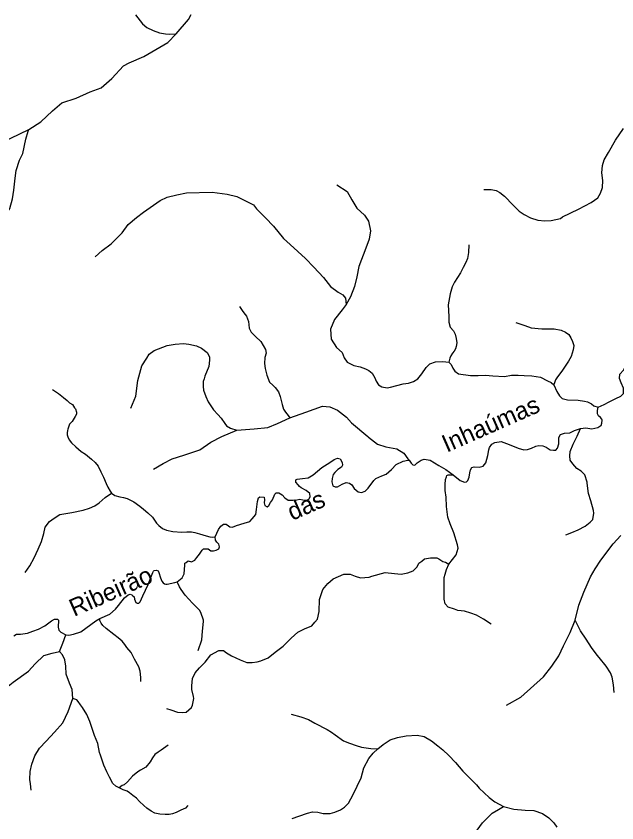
# Model space of a CAD drawing. Extents: x 436.3 to 500.4, y 8231 to 8286.4.
# Drawn here: x 465.31 to 472.13, y 8266.93 to 8276.08 of the extents above; entities that cross this region are included whole.
import ezdxf
from ezdxf.enums import TextEntityAlignment as Align

# ---------------------------------------------------------------- set-up
doc = ezdxf.new("R2010")
doc.units = 0
doc.header["$LTSCALE"] = 0.08
doc.linetypes.add('LONG_DASHED', pattern=[7.5, 6, -1.5])
doc.layers.add('61', color=7, linetype='Continuous')
doc.layers.add('9', color=7, linetype='LONG_DASHED', lineweight=25)

msp = doc.modelspace()

# ---------------------------------------------------------------- linework, layer by layer
at = {"layer": '9'}
for points in [[(466.6698, 8276.0975), (466.7493, 8275.9956), (466.7975, 8275.9512), (466.8677, 8275.918), (466.9416, 8275.8923), (467.0083, 8275.8813), (467.0526, 8275.8777), (467.1302, 8275.8815)], [(467.1302, 8275.8815), (467.2683, 8276.0433), (467.3012, 8276.101)], [(465.4558, 8274.796), (465.594, 8274.8835), (465.727, 8275.0083), (465.8334, 8275.0975), (465.993, 8275.151), (466.1526, 8275.2225), (466.2767, 8275.2671), (466.4009, 8275.3741), (466.5337, 8275.5167), (466.5958, 8275.5524), (466.7643, 8275.6238), (467.0342, 8275.7812), (467.1302, 8275.8815)], [(463.7903, 8273.8492), (463.8702, 8273.9116), (463.9855, 8273.9917), (464.1185, 8274.1253), (464.2072, 8274.1699), (464.3226, 8274.2323), (464.4823, 8274.3213), (464.6331, 8274.4104), (464.7356, 8274.4873), (464.9259, 8274.5708), (465.1211, 8274.6334), (465.2541, 8274.6958), (465.4558, 8274.796)], [(465.1525, 8273.7927), (465.2093, 8273.8456), (465.2399, 8273.8983), (465.2703, 8274.0082), (465.2877, 8274.1049), (465.3006, 8274.2411), (465.3136, 8274.3291), (465.3528, 8274.4478), (465.3877, 8274.5225), (465.4225, 8274.6851), (465.4486, 8274.7773), (465.4558, 8274.796)], [(470.6236, 8274.1144), (470.7041, 8274.1144), (470.7615, 8274.1029), (470.8038, 8274.0798), (470.8574, 8274.0374), (470.9531, 8273.9374), (471.0221, 8273.8682), (471.0796, 8273.8296), (471.1524, 8273.7912), (471.2329, 8273.7643), (471.3134, 8273.7567), (471.3862, 8273.7605), (471.4936, 8273.7837), (471.5165, 8273.803), (471.6968, 8273.8919), (471.8387, 8273.9652), (471.9154, 8274.0192), (471.9461, 8274.0731), (471.9691, 8274.1348), (471.973, 8274.2157), (471.9615, 8274.3042), (471.9703, 8274.3868), (471.9895, 8274.4522), (472.0356, 8274.5331), (472.1161, 8274.6757), (472.2082, 8274.8067)], [(468.9552, 8274.166), (469.072, 8274.0926), (469.1231, 8273.9972), (469.1815, 8273.9018), (469.2692, 8273.8211), (469.313, 8273.755), (469.3348, 8273.6449), (469.3203, 8273.5496), (469.2837, 8273.4468), (469.2035, 8273.2413), (469.1815, 8273.1238), (469.1523, 8273.0137), (469.1085, 8272.8963), (469.0574, 8272.8082)], [(466.2111, 8273.349), (466.2913, 8273.4225), (466.3934, 8273.496), (466.5175, 8273.6208), (466.583, 8273.7163), (466.6779, 8273.7972), (466.7582, 8273.856), (466.9479, 8273.9883), (467.0281, 8274.0251), (467.1375, 8274.0547), (467.247, 8274.0768), (467.539, 8274.0844), (467.707, 8274.0626), (467.8165, 8274.0334), (468.0063, 8273.9381), (468.0428, 8273.894), (468.145, 8273.7914), (468.2327, 8273.696), (468.3495, 8273.5566), (468.4225, 8273.4906), (468.5101, 8273.4098), (468.5977, 8273.3292), (468.6925, 8273.2338), (468.8021, 8273.1164), (468.8823, 8273.0137), (468.9698, 8272.9476), (469.0209, 8272.9183), (469.0501, 8272.8816), (469.0574, 8272.8082)], [(470.4501, 8273.4879), (470.4463, 8273.3997), (470.4348, 8273.3306), (470.4157, 8273.2846), (470.389, 8273.2272), (470.3568, 8273.1695), (470.2876, 8273.0616), (470.2608, 8273.0076), (470.2378, 8272.9305), (470.2185, 8272.8033), (470.226, 8272.6723), (470.226, 8272.6068), (470.2413, 8272.5528), (470.2758, 8272.5105), (470.295, 8272.4719), (470.3064, 8272.4218), (470.3141, 8272.3756), (470.3064, 8272.3332), (470.2986, 8272.3062), (470.2834, 8272.2792), (470.268, 8272.2561), (470.2488, 8272.2253), (470.2373, 8272.1983), (470.2248, 8272.1555)], [(467.8468, 8272.7854), (467.8875, 8272.7309), (467.9146, 8272.6946), (467.9281, 8272.6764), (467.9507, 8272.6174), (467.9597, 8272.5401), (467.9823, 8272.4946), (468.032, 8272.4447), (468.0908, 8272.3901), (468.1179, 8272.3448), (468.145, 8272.2993), (468.1495, 8272.2584), (468.1359, 8272.2084), (468.1314, 8272.1403), (468.1403, 8272.0811), (468.1585, 8272.0085), (468.1901, 8271.9267), (468.2262, 8271.895), (468.2533, 8271.8677), (468.2894, 8271.8177), (468.312, 8271.7632), (468.3345, 8271.6724), (468.3481, 8271.6224), (468.3707, 8271.5861), (468.4023, 8271.5497), (468.4217, 8271.5227)], [(469.0574, 8272.8082), (469.0139, 8272.7471), (468.9264, 8272.637), (468.883, 8272.5289), (468.8898, 8272.4169), (468.9481, 8272.3215), (469.0137, 8272.2628), (469.0356, 8272.2041), (469.0721, 8272.1529), (469.145, 8272.1161), (469.218, 8272.1015), (469.278, 8272.0784), (469.3163, 8272.0591), (469.3545, 8272.0283), (469.3852, 8271.9782), (469.4005, 8271.9398), (469.4273, 8271.8973), (469.4656, 8271.8743), (469.5231, 8271.8627), (469.5614, 8271.8705), (469.7071, 8271.909), (469.7684, 8271.9167), (469.8221, 8271.936), (469.872, 8271.9668), (469.918, 8272.0207), (469.9679, 8272.0939), (470.0101, 8272.1362), (470.0714, 8272.1594), (470.1557, 8272.1632), (470.2248, 8272.1555)], [(470.9866, 8272.6059), (471.0862, 8272.5712), (471.1591, 8272.5443), (471.2819, 8272.5328), (471.42, 8272.5329), (471.5006, 8272.5175), (471.5504, 8272.4944), (471.5849, 8272.4674), (471.6078, 8272.429), (471.627, 8272.3904), (471.6423, 8272.3441), (471.6346, 8272.2941), (471.6115, 8272.217), (471.5846, 8272.1669), (471.5077, 8272.0513), (471.4578, 8271.9896), (471.4347, 8271.955), (471.4155, 8271.8972)], [(466.6156, 8271.6332), (466.6704, 8271.7669), (466.6939, 8271.9475), (466.7408, 8272.1126), (466.7955, 8272.1991), (466.8238, 8272.2468), (466.8799, 8272.2879), (467.0278, 8272.3445), (467.1196, 8272.3599), (467.2115, 8272.3651), (467.2726, 8272.36), (467.3594, 8272.3396), (467.4154, 8272.314), (467.4817, 8272.2628), (467.5073, 8272.2167), (467.5073, 8272.1756), (467.5021, 8272.1038), (467.4562, 8271.9962), (467.446, 8271.9653), (467.4358, 8271.9346), (467.4358, 8271.8782), (467.4408, 8271.8372), (467.4662, 8271.7654), (467.4917, 8271.7039), (467.5529, 8271.6117), (467.6039, 8271.5605), (467.6395, 8271.5195), (467.6803, 8271.458), (467.7007, 8271.4324), (467.7466, 8271.4069), (467.8198, 8271.381)], [(471.9178, 8271.643), (471.9891, 8271.6733), (472.043, 8271.7029), (472.1216, 8271.7424), (472.1762, 8271.7697), (472.2056, 8271.7993), (472.2056, 8271.8583), (472.1812, 8271.9209), (472.1617, 8271.97), (472.1666, 8272.0193), (472.2059, 8272.0637), (472.2305, 8272.1081), (472.26, 8272.1573), (472.2747, 8272.1968), (472.2894, 8272.2264), (472.3238, 8272.2461), (472.3975, 8272.2462), (472.4465, 8272.2316), (472.5043, 8272.1873)], [(470.2248, 8272.1555), (470.2516, 8272.1286), (470.2707, 8272.0863), (470.2937, 8272.0515), (470.3359, 8272.0207), (470.4722, 8272.0043), (470.5566, 8272.0043), (470.6409, 8272.0082), (470.7253, 8272.0005), (470.8556, 8271.9928), (470.9362, 8272.0083), (471.0129, 8272.0083), (471.078, 8272.0044), (471.1663, 8272.0006), (471.266, 8271.9853), (471.3427, 8271.9429), (471.3849, 8271.9237), (471.4155, 8271.8972)], [(465.7249, 8271.8458), (465.7952, 8271.7971), (465.8492, 8271.7537), (465.8925, 8271.7211), (465.9194, 8271.694), (465.952, 8271.6723), (465.9743, 8271.6374), (465.9864, 8271.6237), (465.9985, 8271.5856), (465.9985, 8271.5626), (465.9818, 8271.5382), (465.9484, 8271.4817), (465.9193, 8271.4493), (465.9014, 8271.3959), (465.8971, 8271.3801), (465.8928, 8271.3531), (465.8928, 8271.3289), (465.8985, 8271.3089), (465.9141, 8271.2748), (465.9425, 8271.2391), (465.9907, 8271.1936), (466.0503, 8271.1423), (466.0999, 8271.1096), (466.168, 8271.0527), (466.2106, 8271.0156), (466.2431, 8270.973), (466.2747, 8270.9106), (466.3045, 8270.848), (466.3356, 8270.7769), (466.3554, 8270.737), (466.3809, 8270.6914), (466.3947, 8270.6664)], [(471.4155, 8271.8972), (471.45, 8271.8198), (471.4806, 8271.7736), (471.5112, 8271.7428), (471.5726, 8271.7275), (471.6915, 8271.7237), (471.7644, 8271.7122), (471.7989, 8271.7045), (471.8449, 8271.6815), (471.8718, 8271.6584), (471.9178, 8271.643)], [(468.4217, 8271.5227), (468.6015, 8271.5856), (468.7891, 8271.6564), (468.8751, 8271.6486), (468.961, 8271.6093), (469.0646, 8271.5303), (469.1193, 8271.4675), (469.3068, 8271.3104), (469.3146, 8271.3026), (469.4162, 8271.2241), (469.5099, 8271.1927), (469.635, 8271.1692), (469.7131, 8271.1221), (469.76, 8271.0593), (469.774, 8271.0423)], [(471.719, 8271.4025), (471.7778, 8271.4074), (471.8464, 8271.3977), (471.9152, 8271.4125), (471.9397, 8271.4273), (471.9544, 8271.4371), (471.9594, 8271.4618), (471.9643, 8271.4962), (471.9594, 8271.506), (471.9447, 8271.5256), (471.9251, 8271.5454), (471.9104, 8271.5699), (471.9105, 8271.6043), (471.9178, 8271.643)], [(467.8198, 8271.381), (468.0151, 8271.3969), (468.1715, 8271.4126), (468.2809, 8271.4598), (468.4217, 8271.5227)], [(466.8738, 8270.9408), (466.9832, 8271.0036), (467.0849, 8271.0587), (467.2177, 8271.098), (467.3976, 8271.1609), (467.5227, 8271.2473), (467.6478, 8271.3103), (467.8198, 8271.381)], [(470.2736, 8270.8743), (470.3518, 8270.8104), (470.4009, 8270.7908), (470.424, 8270.7972), (470.4406, 8270.8119), (470.4553, 8270.8489), (470.4647, 8270.8989), (470.4701, 8270.9338), (470.4843, 8270.9579), (470.5138, 8270.9678), (470.5696, 8270.9629), (470.6138, 8270.9729), (470.6433, 8271.0122), (470.6678, 8271.0958), (470.6777, 8271.1598), (470.6875, 8271.1843), (470.712, 8271.2236), (470.7464, 8271.2433), (470.82, 8271.2533), (470.9082, 8271.2188), (471.011, 8271.1795), (471.0748, 8271.1599), (471.1189, 8271.1649), (471.163, 8271.1796), (471.2121, 8271.1993), (471.2464, 8271.2091), (471.2906, 8271.2043), (471.3297, 8271.1895), (471.3738, 8271.1601), (471.413, 8271.1551), (471.4376, 8271.1551), (471.4572, 8271.1798), (471.472, 8271.2289), (471.4721, 8271.2978), (471.4933, 8271.3334), (471.5374, 8271.3483), (471.5963, 8271.3532), (471.6503, 8271.3778), (471.719, 8271.4025)], [(471.5523, 8270.1963), (471.621, 8270.2231), (471.6935, 8270.2499), (471.7737, 8270.2921), (471.8272, 8270.3379), (471.8577, 8270.3686), (471.8692, 8270.4412), (471.8655, 8270.4717), (471.8351, 8270.5826), (471.8085, 8270.6628), (471.7934, 8270.7813), (471.7934, 8270.7927), (471.7667, 8270.8768), (471.7248, 8270.9189), (471.6791, 8270.9494), (471.6334, 8270.999), (471.603, 8271.0411), (471.5991, 8271.0908), (471.6031, 8271.1405), (471.6375, 8271.2247), (471.6796, 8271.3165), (471.719, 8271.4025)], [(467.5711, 8270.1719), (467.6105, 8270.2567), (467.6371, 8270.2916), (467.6688, 8270.3174), (467.6955, 8270.3159), (467.7248, 8270.2962), (467.7396, 8270.2864), (467.7689, 8270.2815), (467.813, 8270.3012), (467.9012, 8270.3258), (467.9649, 8270.3456), (467.9942, 8270.375), (468.0335, 8270.4242), (468.0433, 8270.4832), (468.0533, 8270.5717), (468.0631, 8270.6159), (468.0778, 8270.6258), (468.1267, 8270.621), (468.1316, 8270.5914), (468.1267, 8270.557), (468.1365, 8270.5275), (468.1609, 8270.5127), (468.1806, 8270.5276), (468.2002, 8270.562), (468.2246, 8270.5914), (468.2492, 8270.6554), (468.2639, 8270.6701), (468.2933, 8270.6702), (468.3325, 8270.6505), (468.3619, 8270.6161), (468.4009, 8270.5866), (468.4549, 8270.5866), (468.499, 8270.5916), (468.5332, 8270.6014), (468.5675, 8270.5916), (468.5822, 8270.5867), (468.6115, 8270.5867), (468.6361, 8270.6015), (468.6508, 8270.6261), (468.6459, 8270.6654), (468.6068, 8270.6998), (468.5481, 8270.7293), (468.5284, 8270.7441), (468.5138, 8270.7637), (468.4893, 8270.7932), (468.4893, 8270.8178), (468.5041, 8270.8277), (468.5628, 8270.8326), (468.6266, 8270.8425), (468.6853, 8270.8769), (468.7833, 8270.9605), (468.8726, 8271.0164), (468.9216, 8271.0508), (468.9608, 8271.0657), (468.9902, 8271.0559), (469.0146, 8271.0165), (469.0194, 8270.987), (469.0048, 8270.9624), (468.9655, 8270.9377), (468.9312, 8270.9033), (468.9116, 8270.8788), (468.9018, 8270.8344), (468.8969, 8270.7951), (468.9066, 8270.7508), (468.936, 8270.741), (468.9605, 8270.741), (469.0143, 8270.7705), (469.0584, 8270.7903), (469.0976, 8270.7805), (469.1222, 8270.7607), (469.1514, 8270.7215), (469.1955, 8270.6822), (469.2347, 8270.6772), (469.2739, 8270.692), (469.3082, 8270.7264), (469.372, 8270.8101), (469.3965, 8270.8346), (469.4651, 8270.8641), (469.5142, 8270.8839), (469.573, 8270.938), (469.6269, 8270.9921), (469.7054, 8271.0314), (469.7592, 8271.0413), (469.774, 8271.0423)], [(469.774, 8271.0423), (469.7984, 8271.0069), (469.8163, 8270.9896), (469.8376, 8270.9873), (469.8663, 8271.012), (469.9099, 8271.0436), (469.9458, 8271.0539), (470.014, 8271.0414), (470.112, 8270.9824), (470.1903, 8270.9381), (470.2736, 8270.8743)], [(470.2262, 8269.8611), (470.3093, 8269.9689), (470.329, 8270.0424), (470.3242, 8270.0816), (470.2803, 8270.2187), (470.2414, 8270.3216), (470.2122, 8270.3951), (470.1975, 8270.515), (470.1928, 8270.6228), (470.1831, 8270.6964), (470.1832, 8270.765), (470.1881, 8270.8239), (470.1979, 8270.8533), (470.2028, 8270.868), (470.216, 8270.8764), (470.227, 8270.8764), (470.2736, 8270.8743)], [(465.4152, 8269.7659), (465.4694, 8269.8418), (465.5182, 8269.9339), (465.5616, 8270.0315), (465.5996, 8270.1182), (465.6267, 8270.2103), (465.643, 8270.2809), (465.6917, 8270.3459), (465.7459, 8270.3839), (465.8107, 8270.4273), (465.9458, 8270.4492), (466.0756, 8270.4763), (466.1459, 8270.4981), (466.2053, 8270.5252), (466.254, 8270.5578), (466.3243, 8270.6175), (466.3947, 8270.6664)], [(466.3947, 8270.6664), (466.4334, 8270.6415), (466.4916, 8270.6245), (466.5314, 8270.6195), (466.5744, 8270.6082), (466.6475, 8270.5706), (466.7167, 8270.5218), (466.7598, 8270.4879), (466.8084, 8270.4429), (466.8608, 8270.394), (466.9057, 8270.3283), (466.9319, 8270.302), (466.9749, 8270.2682), (467.0198, 8270.2475), (467.0929, 8270.2326), (467.194, 8270.2251), (467.2491, 8270.2281), (467.3034, 8270.23), (467.3408, 8270.2225), (467.3952, 8270.2056), (467.47, 8270.185), (467.5112, 8270.1738), (467.5449, 8270.17), (467.5711, 8270.1719)], [(467.1392, 8269.663), (467.197, 8269.7074), (467.2198, 8269.7532), (467.2275, 8269.8522), (467.2275, 8269.875), (467.2428, 8269.8827), (467.2656, 8269.898), (467.3035, 8269.8903), (467.3416, 8269.9056), (467.3644, 8269.9361), (467.3949, 8269.9743), (467.4253, 8270.02), (467.4405, 8270.0352), (467.4937, 8270.0352), (467.5241, 8270.0124), (467.5545, 8270.0124), (467.5849, 8270.02), (467.6152, 8270.0353), (467.6229, 8270.0582), (467.6153, 8270.0887), (467.5926, 8270.1115), (467.5768, 8270.1343), (467.5711, 8270.1719)], [(471.6582, 8269.2259), (471.7017, 8269.395), (471.7587, 8269.5445), (471.8325, 8269.718), (471.8847, 8269.8092), (471.9497, 8269.909), (472.0886, 8270.0913), (472.1754, 8270.1868)], [(467.0218, 8268.2252), (467.0686, 8268.2076), (467.1444, 8268.1843), (467.2029, 8268.1785), (467.2437, 8268.1843), (467.3022, 8268.2369), (467.3138, 8268.2603), (467.3315, 8268.3363), (467.3257, 8268.3597), (467.3083, 8268.4415), (467.3084, 8268.4825), (467.3142, 8268.5644), (467.3435, 8268.6287), (467.3962, 8268.6872), (467.4606, 8268.7516), (467.5249, 8268.8336), (467.6125, 8268.8804), (467.6652, 8268.8804), (467.7001, 8268.857), (467.7585, 8268.8219), (467.8577, 8268.7752), (467.9336, 8268.7459), (467.992, 8268.7459), (468.0504, 8268.7518), (468.0913, 8268.7636), (468.1731, 8268.7987), (468.255, 8268.8631), (468.3426, 8268.9333), (468.4363, 8269.0212), (468.5123, 8269.0915), (468.5882, 8269.1267), (468.67, 8269.1619), (468.7052, 8269.2028), (468.7345, 8269.238), (468.752, 8269.3258), (468.7581, 8269.4605), (468.7943, 8269.5736), (468.8529, 8269.6439), (468.9113, 8269.6967), (469.034, 8269.7495), (469.1041, 8269.7495), (469.1625, 8269.7261), (469.2209, 8269.7086), (469.3202, 8269.7145), (469.3495, 8269.7262), (469.5014, 8269.7674), (469.6065, 8269.7557), (469.6825, 8269.7498), (469.7601, 8269.7625), (469.8186, 8269.786), (469.8654, 8269.8329), (469.8829, 8269.8739), (469.9181, 8269.8974), (469.9473, 8269.9208), (470.0174, 8269.9326), (470.0875, 8269.9326), (470.1108, 8269.9209), (470.1576, 8269.8916), (470.1868, 8269.8858), (470.2262, 8269.8611)], [(470.7042, 8269.1804), (470.6163, 8269.239), (470.5382, 8269.283), (470.4747, 8269.3074), (470.4013, 8269.327), (470.328, 8269.3367), (470.289, 8269.3513), (470.2157, 8269.3758), (470.1815, 8269.41), (470.1718, 8269.4639), (470.172, 8269.6156), (470.1722, 8269.7092), (470.1821, 8269.7485), (470.1968, 8269.8023), (470.2262, 8269.8611)], [(466.2633, 8269.2461), (466.3751, 8269.293), (466.4428, 8269.3496), (466.4767, 8269.3947), (466.5444, 8269.4795), (466.5863, 8269.5147), (466.6092, 8269.5223), (466.627, 8269.5147), (466.6397, 8269.5045), (466.6524, 8269.4918), (466.6574, 8269.4663), (466.6625, 8269.446), (466.6726, 8269.4256), (466.6853, 8269.4205), (466.7056, 8269.4205), (466.7209, 8269.4358), (466.7515, 8269.5021), (466.8126, 8269.632), (466.8483, 8269.7289), (466.8636, 8269.7671), (466.8713, 8269.7823), (466.8815, 8269.7901), (466.9069, 8269.7952), (466.9247, 8269.7875), (466.9348, 8269.7672), (466.95, 8269.7085), (466.9652, 8269.6703), (466.9804, 8269.6499), (466.9982, 8269.6397), (467.0109, 8269.6346), (467.0261, 8269.6346), (467.1134, 8269.654), (467.1392, 8269.663)], [(467.3805, 8268.8806), (467.421, 8269.0021), (467.428, 8269.1033), (467.4416, 8269.2112), (467.4416, 8269.2247), (467.408, 8269.3124), (467.3946, 8269.3394), (467.3139, 8269.4203), (467.2331, 8269.5088), (467.1861, 8269.5762), (467.1659, 8269.6033), (467.1392, 8269.663)], [(465.2854, 8269.047), (465.3184, 8269.0675), (465.3636, 8269.0675), (465.4425, 8269.0788), (465.5046, 8269.1014), (465.5667, 8269.124), (465.64, 8269.1635), (465.7134, 8269.2201), (465.7472, 8269.237), (465.7811, 8269.237), (465.7923, 8269.2257), (465.7922, 8269.1467), (465.7978, 8269.1128), (465.8204, 8269.0903), (465.8767, 8269.0606)], [(465.8767, 8269.0606), (465.9105, 8269.0564), (465.9633, 8269.067), (466.0479, 8269.0952), (466.2172, 8269.2195), (466.2633, 8269.2461)], [(466.7268, 8268.5306), (466.7296, 8268.5768), (466.7217, 8268.6465), (466.7057, 8268.6975), (466.6576, 8268.7833), (466.6175, 8268.8611), (466.5694, 8268.9175), (466.548, 8268.9522), (466.5159, 8268.9898), (466.4731, 8269.0274), (466.4222, 8269.0622), (466.3339, 8269.132), (466.2956, 8269.1661), (466.2778, 8269.1937), (466.2646, 8269.2229), (466.2633, 8269.2461)], [(470.8781, 8268.2622), (471.0423, 8268.3545), (471.298, 8268.5843), (471.3934, 8268.7057), (471.4715, 8268.8227), (471.5279, 8268.9355), (471.6017, 8269.0872), (471.6582, 8269.2259)], [(472.0997, 8268.4075), (472.0929, 8268.4936), (472.0793, 8268.5796), (472.0587, 8268.6278), (472.0106, 8268.7035), (471.9315, 8268.8033), (471.9075, 8268.8309), (471.8422, 8268.9169), (471.7837, 8269.0099), (471.7184, 8269.1063), (471.6582, 8269.2259)], [(465.8036, 8268.8703), (465.8431, 8268.9659), (465.8767, 8269.0606)], [(465.185, 8268.4466), (465.2807, 8268.5224), (465.4521, 8268.6459), (465.5279, 8268.7296), (465.6274, 8268.8244), (465.7217, 8268.8513), (465.8036, 8268.8703)], [(465.9567, 8268.3392), (465.9486, 8268.4395), (465.9196, 8268.5133), (465.883, 8268.6154), (465.8764, 8268.7031), (465.8663, 8268.7759), (465.8406, 8268.8345), (465.8036, 8268.8703)], [(465.4839, 8267.2955), (465.4772, 8267.3696), (465.4706, 8267.4167), (465.4707, 8267.5109), (465.491, 8267.5916), (465.5248, 8267.6859), (465.5788, 8267.7735), (465.653, 8267.8542), (465.7474, 8267.9552), (465.8419, 8268.063), (465.9026, 8268.191), (465.9567, 8268.3392)], [(466.4824, 8267.323), (466.4464, 8267.341), (466.4104, 8267.3744), (466.3745, 8267.4439), (466.3438, 8267.5056), (466.3104, 8267.5802), (466.2694, 8267.6933), (466.2607, 8267.7229), (466.2403, 8267.8283), (466.2044, 8267.9158), (466.1505, 8268.0753), (466.1146, 8268.155), (466.0659, 8268.2348), (466.045, 8268.2667), (466.0168, 8268.3028), (466.0014, 8268.3234), (465.9567, 8268.3392)], [(468.4347, 8268.1581), (468.5459, 8268.1292), (468.6329, 8268.1002), (468.7031, 8268.0567), (468.8433, 8267.9865), (468.8941, 8267.9551), (468.9327, 8267.9236), (469.0294, 8267.8584), (469.0972, 8267.8293), (469.1721, 8267.8028), (469.2326, 8267.7859), (469.339, 8267.7691), (469.4174, 8267.7678)], [(469.4174, 8267.7678), (469.4774, 8267.8173), (469.5586, 8267.8667), (469.6433, 8267.895), (469.7386, 8267.9127), (469.8635, 8267.9199), (469.9446, 8267.9059), (470.0292, 8267.8565), (470.0997, 8267.8001), (470.1561, 8267.7543), (470.223, 8267.6909), (470.3005, 8267.6098), (470.3851, 8267.5111), (470.4662, 8267.4301), (470.5402, 8267.356), (470.5684, 8267.3208), (470.6812, 8267.2151), (470.7461, 8267.1642), (470.845, 8267.1125)], [(467.0396, 8267.8066), (467.0122, 8267.7874), (466.9604, 8267.7493), (466.925, 8267.7275), (466.8894, 8267.7003), (466.8622, 8267.6648), (466.8349, 8267.6185), (466.7858, 8267.5585), (466.7257, 8267.523), (466.6957, 8267.5068), (466.633, 8267.455), (466.5784, 8267.3923), (466.5402, 8267.3595), (466.5183, 8267.3487), (466.4824, 8267.323)], [(468.4464, 8266.9766), (468.5237, 8267.0037), (468.619, 8267.0355), (468.6789, 8267.0496), (468.7389, 8267.0461), (468.7988, 8267.032), (468.8764, 8267.032), (468.9293, 8267.0462), (468.9963, 8267.0744), (469.0422, 8267.1062), (469.0846, 8267.1486), (469.1376, 8267.2474), (469.2295, 8267.4379), (469.2613, 8267.5508), (469.3151, 8267.6584), (469.3645, 8267.7184), (469.4174, 8267.7678)], [(467.264, 8267.1224), (467.2358, 8267.0941), (467.1843, 8267.0684), (467.1302, 8267.0427), (467.0865, 8267.0273), (467.0505, 8267.0196), (467.0042, 8267.0196), (466.9425, 8267.0248), (466.8886, 8267.0376), (466.8448, 8267.0607), (466.7985, 8267.0942), (466.7626, 8267.125), (466.7137, 8267.1688), (466.6778, 8267.2047), (466.6392, 8267.2355), (466.6007, 8267.2664), (466.5724, 8267.2845), (466.5288, 8267.3024), (466.4824, 8267.323)], [(469.3908, 8266.1318), (469.5072, 8266.2352), (469.6043, 8266.3193), (469.6821, 8266.4099), (469.7598, 8266.5457), (469.8374, 8266.617), (469.9086, 8266.6494), (469.9927, 8266.6494), (470.1415, 8266.6496), (470.2709, 8266.6755), (470.4069, 8266.7015), (470.4522, 8266.7274), (470.504, 8266.7857), (470.6077, 8266.928), (470.6789, 8266.9993), (470.7178, 8267.0381), (470.7889, 8267.077), (470.845, 8267.1125)], [(470.845, 8267.1125), (470.9613, 8267.0798), (471.0919, 8267.0694), (471.1907, 8267.0659), (471.2895, 8267.0342), (471.36, 8266.985), (471.4165, 8266.9251), (471.4517, 8266.8757)]]:
    msp.add_lwpolyline(points, dxfattribs=at)

# ---------------------------------------------------------------- texts
at = {"layer": '61'}
msp.add_text('Ribeirão                       das                    Inhaúmas', height=0.2, rotation=23.771, dxfattribs=at).set_placement((468.6237, 8270.4309), align=Align.CENTER)

doc.saveas('drawing.dxf')
